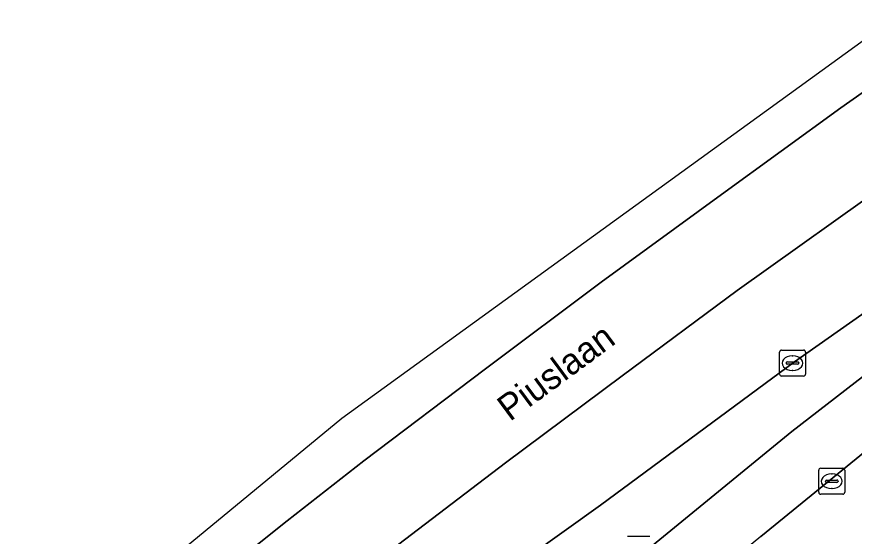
# Model space of a CAD drawing. Extents: x 162344 to 162869, y 381217 to 381818.
# Drawn here: x 162449.62 to 162481.8, y 381769.46 to 381789.43 of the extents above; entities that cross this region are included whole.
import ezdxf

# ---------------------------------------------------------------- set-up
doc = ezdxf.new("R2010")
doc.units = 0
for name, color, linetype in [('IMGEO_Berm_groen', 7, 'Continuous'), ('IMGEO_Fietspad_open', 7, 'Continuous'), ('IMGEO_Haag', 7, 'Continuous'), ('IMGEO_Kolk', 7, 'Continuous'), ('IMGEO_Openbare_ruimte_label', 7, 'Continuous'), ('IMGEO_Rijbaan_regionaal_gesloten', 7, 'Continuous'), ('IMGEO_Rioolput', 7, 'Continuous'), ('IMGEO_Verkeerseiland_groen', 7, 'Continuous')]:
    doc.layers.add(name, color=color, linetype=linetype)

msp = doc.modelspace()

# ---------------------------------------------------------------- linework, layer by layer
at = {"layer": 'IMGEO_Berm_groen'}
msp.add_lwpolyline([(162485.569, 381771.54), (162486.346, 381772.165), (162499.033, 381781.642), (162500.475, 381782.734), (162498.716, 381785.09), (162498.222, 381784.754), (162492.604, 381780.797), (162491.487, 381780.055), (162488.724, 381777.94), (162487.946, 381777.388), (162484.993, 381774.972), (162478.211, 381769.449), (162471.4, 381763.826), (162457.878, 381752.522), (162455.794, 381750.801), (162451.521, 381747.272), (162447.905, 381744.275), (162433.442, 381732.29), (162428.876, 381728.513), (162426.389, 381726.442), (162426.314, 381726.37), (162428.207, 381724.094), (162451.823, 381743.637), (162459.348, 381749.88)], close=True, dxfattribs=at)
at = {"layer": 'IMGEO_Fietspad_open'}
msp.add_lwpolyline([(162478.211, 381769.449), (162484.993, 381774.972), (162487.946, 381777.388), (162488.724, 381777.94), (162491.487, 381780.055), (162492.604, 381780.797), (162498.222, 381784.754), (162498.716, 381785.09), (162498.927, 381785.234), (162497.586, 381787.208), (162497.383, 381787.061), (162496.837, 381786.624), (162492.847, 381783.857), (162487.669, 381779.887), (162479.401, 381773.49), (162473.627, 381768.749), (162469.707, 381765.621), (162465.698, 381762.373), (162457.272, 381755.297), (162454.619, 381753.172)], dxfattribs=at)
at = {"layer": 'IMGEO_Haag'}
for points in [[(162479.401, 381773.49), (162487.669, 381779.887), (162492.847, 381783.857), (162496.837, 381786.624), (162497.383, 381787.061), (162497.586, 381787.208), (162498.53, 381787.845), (162497.75, 381788.92), (162496.598, 381788.121), (162488.093, 381782.207), (162479.504, 381776.17), (162472.053, 381770.655), (162467.953, 381767.716), (162463.784, 381764.558), (162459.974, 381761.291), (162459.215, 381760.482), (162459.098, 381760.385), (162458.667, 381759.873), (162455.999, 381756.704), (162454.038, 381753.891), (162453.983, 381753.716)], [(162454.619, 381753.172), (162457.272, 381755.297), (162465.698, 381762.373), (162469.707, 381765.621), (162473.627, 381768.749), (162479.401, 381773.49)]]:
    msp.add_lwpolyline(points, dxfattribs=at)
at = {"layer": 'IMGEO_Kolk'}
for p, q in [((162479.005, 381776.615), (162479.857, 381776.615)), ((162478.93, 381775.689), (162478.93, 381776.541)), ((162479.418, 381776.395), (162479.443, 381776.395)), ((162479.931, 381776.541), (162479.931, 381775.689)), ((162479.189, 381776.109), (162479.189, 381776.121)), ((162479.627, 381776.072), (162479.229, 381776.072)), ((162479.232, 381776.158), (162479.63, 381776.158)), ((162479.673, 381776.121), (162479.673, 381776.109)), ((162479.441, 381775.835), (162479.416, 381775.835)), ((162479.857, 381775.615), (162479.005, 381775.615)), ((162480.437, 381771.147), (162480.437, 381771.999)), ((162480.512, 381772.073), (162481.364, 381772.073)), ((162480.925, 381771.853), (162480.95, 381771.853)), ((162481.438, 381771.999), (162481.438, 381771.147)), ((162480.696, 381771.567), (162480.696, 381771.579)), ((162481.134, 381771.53), (162480.736, 381771.53)), ((162480.739, 381771.616), (162481.137, 381771.616)), ((162481.18, 381771.579), (162481.18, 381771.567)), ((162480.948, 381771.293), (162480.923, 381771.293)), ((162481.364, 381771.073), (162480.512, 381771.073))]:
    msp.add_line(p, q, dxfattribs=at)
for points in [[(162479.005, 381776.615), (162479.857, 381776.615)], [(162478.93, 381775.689), (162478.93, 381776.541)], [(162479.931, 381776.541), (162479.931, 381775.689)], [(162479.857, 381775.615), (162479.005, 381775.615)], [(162480.437, 381771.147), (162480.437, 381771.999)], [(162480.512, 381772.073), (162481.364, 381772.073)], [(162481.438, 381771.999), (162481.438, 381771.147)], [(162481.364, 381771.073), (162480.512, 381771.073)]]:
    msp.add_lwpolyline(points, dxfattribs=at)
for centre, radius, start, end in [((162479.007, 381776.539), 0.0765, 91.552, 178.448), ((162479.007, 381776.539), 0.0765, 91.552, 178.448), ((162479.855, 381776.539), 0.0765, 1.552, 88.448), ((162479.855, 381776.539), 0.0765, 1.552, 88.448), ((162479.229, 381776.118), 0.0403, 85.8775, 175.7526), ((162479.226, 381776.108), 0.0366, 178.938, 274.7102), ((162479.63, 381776.115), 0.043, 264.8664, 352.4533), ((162479.634, 381776.12), 0.0386, 1.7309, 96.639), ((162479.007, 381775.691), 0.0765, 181.552, 268.448), ((162479.007, 381775.691), 0.0765, 181.552, 268.448), ((162479.855, 381775.691), 0.0765, 271.552, 358.448), ((162479.855, 381775.691), 0.0765, 271.552, 358.448), ((162480.514, 381771.997), 0.0765, 91.552, 178.448), ((162480.514, 381771.997), 0.0765, 91.552, 178.448), ((162481.362, 381771.997), 0.0765, 1.552, 88.448), ((162481.362, 381771.997), 0.0765, 1.552, 88.448), ((162480.736, 381771.576), 0.0403, 85.8775, 175.7526), ((162480.733, 381771.566), 0.0366, 178.938, 274.7102), ((162481.137, 381771.573), 0.043, 264.8664, 352.4533), ((162481.141, 381771.578), 0.0386, 1.7309, 96.639), ((162480.514, 381771.149), 0.0765, 181.552, 268.448), ((162480.514, 381771.149), 0.0765, 181.552, 268.448), ((162481.362, 381771.149), 0.0765, 271.552, 358.448), ((162481.362, 381771.149), 0.0765, 271.552, 358.448)]:
    msp.add_arc(centre, radius, start, end, dxfattribs=at)
for centre, major_axis, ratio, start_param, end_param in [((162479.417, 381776.115), (-0.387, 0.002), 0.722429, 4.712389, 7.853982), ((162479.442, 381776.115), (-0.39, 0.002), 0.717154, 1.570796, 4.712389), ((162480.924, 381771.573), (-0.387, 0.002), 0.722429, 4.712389, 7.853982), ((162480.949, 381771.573), (-0.39, 0.002), 0.717154, 1.570796, 4.712389)]:
    msp.add_ellipse(centre, major_axis=major_axis, ratio=ratio, start_param=start_param, end_param=end_param, dxfattribs=at)
at = {"layer": 'IMGEO_Rijbaan_regionaal_gesloten'}
for points in [[(162413.937, 381732.148), (162423.062, 381739.723), (162431.872, 381747.037), (162437.95, 381751.987), (162443.678, 381756.767), (162448.118, 381760.406), (162452.532, 381764.078), (162460.004, 381770.05), (162462.961, 381772.361), (162467.63, 381775.893), (162472.077, 381779.228), (162476.706, 381782.594), (162481.29, 381785.927), (162485.993, 381789.244), (162490.703, 381792.409), (162495.443, 381795.528), (162500.303, 381798.654), (162503.485, 381800.7), (162505.352, 381801.9), (162503.213, 381803.804), (162491.496, 381795.301), (162462.115, 381773.979), (162410.314, 381731.264)], [(162507.878, 381799.651), (162505.352, 381801.9), (162503.485, 381800.7), (162500.303, 381798.654), (162495.443, 381795.528), (162490.703, 381792.409), (162485.993, 381789.244), (162481.29, 381785.927), (162476.706, 381782.594), (162472.077, 381779.228), (162467.63, 381775.893), (162462.961, 381772.361), (162460.004, 381770.05), (162452.532, 381764.078), (162448.118, 381760.406), (162443.678, 381756.767), (162437.95, 381751.987), (162431.872, 381747.037), (162423.062, 381739.723), (162413.937, 381732.148)], [(162432.575, 381743.159), (162436.784, 381746.691), (162438.186, 381747.867), (162441.029, 381750.253), (162443.872, 381752.638), (162446.658, 381754.976), (162451.047, 381758.551), (162453.892, 381760.911), (162456.943, 381763.266), (162462.466, 381767.749), (162468.395, 381772.277), (162472.884, 381775.62), (162477.307, 381778.912), (162483.409, 381783.265), (162487.984, 381786.53), (162492.531, 381789.574), (162497.297, 381792.703), (162498.579, 381793.545), (162507.878, 381799.651)], [(162510.314, 381797.483), (162507.878, 381799.651), (162498.579, 381793.545), (162497.297, 381792.703), (162492.531, 381789.574), (162487.984, 381786.53), (162483.409, 381783.265), (162477.307, 381778.912), (162472.884, 381775.62), (162468.395, 381772.277), (162462.466, 381767.749), (162456.943, 381763.266), (162453.892, 381760.911), (162451.047, 381758.551), (162446.658, 381754.976), (162443.872, 381752.638), (162441.029, 381750.253), (162438.186, 381747.867), (162436.784, 381746.691), (162432.575, 381743.159)], [(162467.953, 381767.716), (162472.053, 381770.655), (162479.504, 381776.17), (162488.093, 381782.207), (162496.598, 381788.121), (162497.75, 381788.92), (162500, 381790.48), (162505.352, 381794.191), (162507.455, 381795.639), (162508.461, 381796.323), (162510.032, 381797.37)]]:
    msp.add_lwpolyline(points, dxfattribs=at)
at = {"layer": 'IMGEO_Rioolput'}
msp.add_line((162473.092, 381769.456), (162473.944, 381769.456), dxfattribs=at)
msp.add_lwpolyline([(162473.092, 381769.456), (162473.944, 381769.456)], dxfattribs=at)
at = {"layer": 'IMGEO_Verkeerseiland_groen'}
for points in [[(162510.032, 381797.37), (162508.461, 381796.323), (162507.455, 381795.639), (162505.352, 381794.191), (162500, 381790.48), (162497.75, 381788.92), (162496.598, 381788.121), (162488.093, 381782.207), (162479.504, 381776.17), (162472.053, 381770.655), (162467.953, 381767.716), (162463.784, 381764.558), (162459.974, 381761.291), (162459.215, 381760.482), (162459.098, 381760.385), (162458.667, 381759.873), (162455.999, 381756.704), (162454.038, 381753.891), (162453.983, 381753.716)], [(162454.619, 381753.172), (162457.272, 381755.297), (162465.698, 381762.373), (162469.707, 381765.621), (162473.627, 381768.749), (162479.401, 381773.49), (162487.669, 381779.887), (162492.847, 381783.857), (162496.837, 381786.624), (162497.383, 381787.061), (162497.586, 381787.208), (162498.53, 381787.845), (162510.929, 381796.213)]]:
    msp.add_lwpolyline(points, dxfattribs=at)

# ---------------------------------------------------------------- texts
at = {"layer": 'IMGEO_Openbare_ruimte_label'}
msp.add_text('Piuslaan', height=1, rotation=36.4572, dxfattribs=at).set_placement((162468.567, 381773.848))

doc.saveas('drawing.dxf')
